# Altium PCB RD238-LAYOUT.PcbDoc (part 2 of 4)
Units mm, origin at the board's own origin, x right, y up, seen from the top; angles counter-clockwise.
Board outline 100 x 120 mm, 4 copper layers (Top Layer, GND2, POWER 3, Bottom Layer), stack 1.444 mm thick; 434 components, 174 nets, 1045 pads, 261 vias.
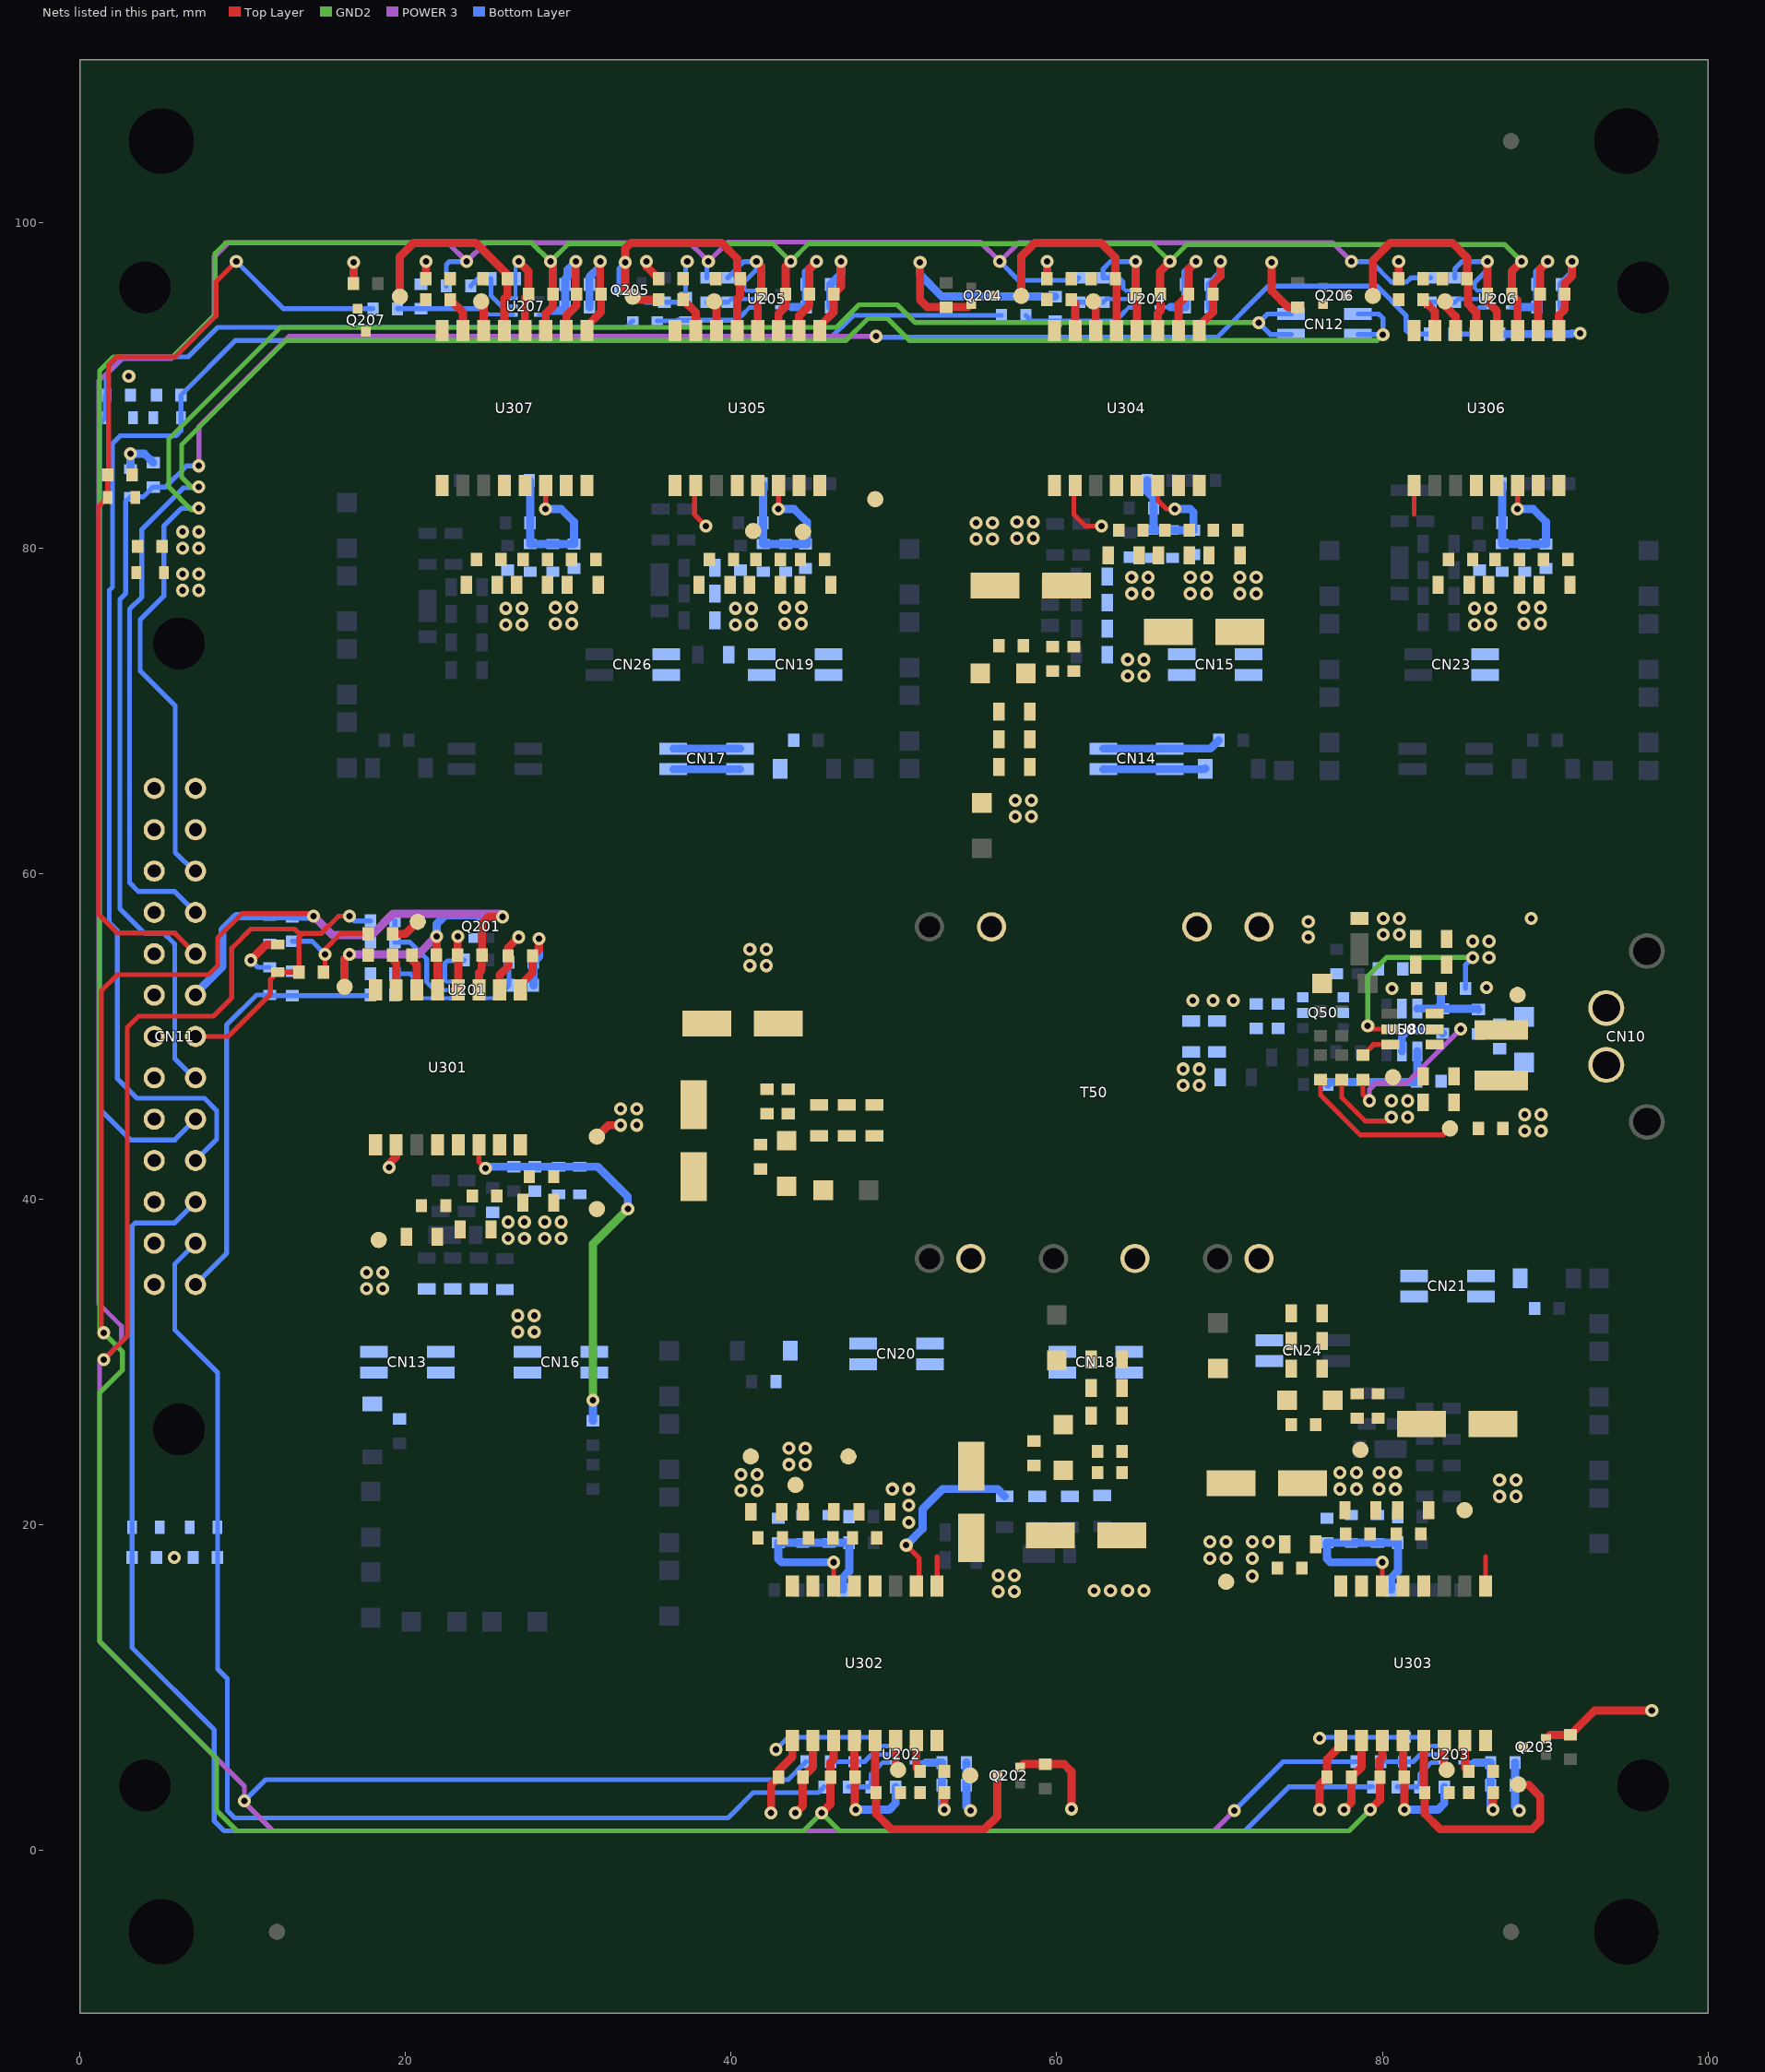
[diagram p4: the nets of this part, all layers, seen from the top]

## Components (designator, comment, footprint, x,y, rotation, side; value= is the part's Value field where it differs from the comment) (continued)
R351 "0" 1608 31.5,22.95 r90 bottom (schematic designator R35)
R352 "0" 1608 43.4,16 r0 bottom (schematic designator R35)
R353 "0" 1608 84,16 r180 bottom (schematic designator R35)
R354 "0" 1608 69,84.15 r180 bottom (schematic designator R35)
R355 "0" 1608 45.35,83.95 r180 bottom (schematic designator R35)
R356 "0" 1608 90.75,83.95 r180 bottom (schematic designator R35)
R357 "0" 1608 24.05,84.15 r0 bottom (schematic designator R35)
R361 "5.6" 2012 22.9,35.45 r90 bottom (schematic designator R36)
R362 "5.6" 2012 58.8,20.8 r270 bottom (schematic designator R36)
R363 "5.6" 2012 84.25,26.2 r270 bottom (schematic designator R36)
R364 "5.6" 2012 62.15,78.25 r180 bottom (schematic designator R36)
R365 "5.6" 2012 38.05,78.8 r180 bottom (schematic designator R36)
R366 "5.6" 2012 83.45,80.25 r180 bottom (schematic designator R36)
R367 "5.6" 2012 23.75,77.6 r180 bottom (schematic designator R36)
R371 "5.6" 2012 21.3,35.45 r90 bottom (schematic designator R37)
R372 "5.6" 2012 56.8,20.8 r270 bottom (schematic designator R37)
R373 "5.6" 2012 82.6,26.2 r270 bottom (schematic designator R37)
R374 "5.6" 2012 62.15,76.65 r180 bottom (schematic designator R37)
R375 "5.6" 2012 38.05,77.2 r180 bottom (schematic designator R37)
R376 "5.6" 2012 83.45,78.65 r180 bottom (schematic designator R37)
R377 "5.6" 2012 23.75,75.95 r180 bottom (schematic designator R37)
R381 "0" 1608 19.628,25.762 r270 bottom (schematic designator R38)
R382 "0" 1608 42,28.8 r180 bottom (schematic designator R38)
R383 "0" 1608 90.1,33.3 r0 bottom (schematic designator R38)
R384 "0" 1608 70.7,68.2 r0 bottom (schematic designator R38)
R385 "0" 1608 44.6,68.2 r0 bottom (schematic designator R38)
R386 "0" 1608 90,68.2 r0 bottom (schematic designator R38)
R387 "0" 1608 19.45,68.2 r180 bottom (schematic designator R38)
R391 "10" 2012 26.1,35.4 r90 bottom (schematic designator R39)
R392 "10" 2012 60.8,20.8 r270 bottom (schematic designator R39)
R393 "10" 2012 80.8,27.15 r270 bottom (schematic designator R39)
R394 "10" 2012 62.15,75.05 r180 bottom (schematic designator R39)
R395 "10" 2012 38.05,75.55 r180 bottom (schematic designator R39)
R396 "10" 2012 83.45,77.05 r180 bottom (schematic designator R39)
R397 "10" 2012 23.75,74.2 r180 bottom (schematic designator R39)
R401 "10" 2012 24.5,35.45 r90 bottom (schematic designator R40)
R402 "10" 2012 62.8,20.85 r270 bottom (schematic designator R40)
R403 "10" 2012 79.05,27.15 r270 bottom (schematic designator R40)
R404 "10" 2012 62.15,73.45 r180 bottom (schematic designator R40)
R405 "10" 2012 38.9,73.45 r180 bottom (schematic designator R40)
R406 "10" 2012 83.45,75.45 r180 bottom (schematic designator R40)
R407 "10" 2012 23.75,72.5 r180 bottom (schematic designator R40)
T50 "750315038" 750315038 62.3,46.55 r270 top
TP10 "5V" TESTPAD_C1 84.15,44.35 r270 top
TP11 "GND" TESTPAD_C1 80.65,47.5 r90 top
TP12 "ABU" TESTPAD_C1 62.25,95.15 r90 top
TP13 "CBU" TESTPAD_C1 57.816,95.489 r90 top
TP14 "ATU" TESTPAD_C1 20.75,57.05 r90 top
TP15 "CTU" TESTPAD_C1 16.25,53.05 r90 top
TP16 "VCC2U" TESTPAD_C1 31.75,39.4 r90 top
TP17 "VEU" TESTPAD_C1 31.75,43.85 r90 top
TP18 "VEEU" TESTPAD_C1 18.35,37.5 r90 top
TP19 "VCC2V" TESTPAD_C1 47.2,24.2 r90 top
TP20 "VEV" TESTPAD_C1 43.95,22.45 r90 top
TP21 "VEEV" TESTPAD_C1 41.2,24.2 r90 top
TP22 "ATV" TESTPAD_C1 50.25,4.95 r270 top
TP23 "ABV" TESTPAD_C1 38.95,95.15 r90 top
TP24 "CTV" TESTPAD_C1 54.684,4.611 r270 top
TP25 "CBV" TESTPAD_C1 33.95,95.45 r90 top
TP26 "VCC2W" TESTPAD_C1 70.4,16.5 r90 top
TP27 "VEW" TESTPAD_C1 78.65,24.6 r90 top
TP28 "VEEW" TESTPAD_C1 85.05,20.9 r90 top
TP29 "ATW" TESTPAD_C1 83.95,4.95 r270 top
TP30 "CTW" TESTPAD_C1 88.35,4.05 r270 top
TP31 "ABW" TESTPAD_C1 83.85,95.15 r90 top
TP32 "CBW" TESTPAD_C1 79.416,95.489 r90 top
TP33 "VCC2B" TESTPAD_C1 41.35,81.05 r90 top
TP34 "VEB" TESTPAD_C1 44.4,81 r90 top
TP35 "VEEB" TESTPAD_C1 48.85,83 r90 top
TP36 "ABR" TESTPAD_C1 24.65,95.15 r90 top
TP37 "CBR" TESTPAD_C1 19.65,95.45 r90 top
TP80 "SW2" TESTPAD_C1 88.3,52.55 r0 top
U50 "LT8306" TSOT23-6 81.2,50.4 r180 bottom
U80 "LMR51430XDDCR" SOT23-6 81.85,50.45 r180 top
U201 "TC7SZ08FE" SOT-553ESV 23.8,52.85 r0 bottom (schematic designator U20)
U202 "TC7SZ08FE" SOT-553ESV 50.462,5.9 r0 bottom (schematic designator U20)
U203 "TC7SZ08FE" SOT-553ESV 84.162,5.9 r0 bottom (schematic designator U20)
U204 "TC7SZ08FE" SOT-553ESV 65.5,95.3 r0 bottom (schematic designator U20)
U205 "TC7SZ08FE" SOT-553ESV 42.2,95.3 r0 bottom (schematic designator U20)
U206 "TC7SZ08FE" SOT-553ESV 87.1,95.3 r0 bottom (schematic designator U20)
U207 "TC7SZ08FE" SOT-553ESV 27.4,94.85 r0 bottom (schematic designator U20)
U301 "TLP5222" SO16L 22.6,48.1 r270 top (schematic designator U30)
U302 "TLP5222" SO16L 48.2,11.5 r90 top (schematic designator U30)
U303 "TLP5222" SO16L 81.9,11.5 r90 top (schematic designator U30)
U304 "TLP5222" SO16L 64.3,88.6 r270 top (schematic designator U30)
U305 "TLP5222" SO16L 41,88.6 r270 top (schematic designator U30)
U306 "TLP5222" SO16L 86.4,88.6 r270 top (schematic designator U30)
U307 "TLP5222" SO16L 26.7,88.6 r270 top (schematic designator U30)
? "Comment" FD 87.9,-5 r180 bottom
? "Comment" FD 12.1,-5 r180 bottom
? "Comment" FD 12.1,-5 r0 top
? "Comment" FD 87.9,-5 r0 top
? "Comment" FD 87.9,105 r180 bottom
? "Comment" FD 87.9,105 r0 top

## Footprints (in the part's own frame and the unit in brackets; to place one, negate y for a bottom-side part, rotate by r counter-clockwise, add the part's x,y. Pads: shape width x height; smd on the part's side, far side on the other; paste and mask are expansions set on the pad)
1608 [mm]
  rect 0.7x0.8 smd mask+0: 1(-0.75,0) 2(0.75,0)
  silkscreen extent -1.33,-0.63 1.33,0.63
2012 [mm]
  rect 0.7x1.1 smd mask+0: 1(-0.95,0) 2(0.95,0)
  silkscreen extent -1.53,-0.77 1.53,0.77
4020 [mm]
  rect 1.2x3.3 smd mask+0: 1(-1.55,0) 2(1.55,0)
  silkscreen extent -2.53,-2.3 2.53,2.3
750315038 [mm]
  round 1.8 hole 1.3 mask+0: 1(-10.19,10.12) 2(-10.19,6.31) 5(-10.19,-6.31) 6(-10.19,-10.12) 7(10.19,-10.12) 8(10.19,-7.58) 10(10.19,-2.5) 11(10.19,2.5) 13(10.19,7.58) 14(10.19,10.12)
  silkscreen extent -13.46,-11.96 12.21,11.96
62300421021 [mm]
  rect 0.74x1.7 smd mask+0: 1(-0.635,-2.05) 2(-0.635,2.05) 3(0.635,-2.05) 4(0.635,2.05)
  silkscreen extent -1.77,-3.94 1.77,3.28
ESC [mm]
  rect 0.6x0.8 smd mask+0: 1(-0.85,0) 2(0.85,0)
  silkscreen extent -1.78,-0.78 1.53,0.78
FD [mm]
  round 1 smd mask+0: 1(0,0)
  Keep-Out Layer circle w0.05: c0,0 r1.6
S-FLAT [mm]
  rect 1.2x1.2 smd mask+0: 1(-1.4,0) 2(1.4,0)
  silkscreen extent -2.38,-0.98 2.67,0.98
SMD [mm]
  rect 3x1.6 smd mask+0: 1(2.2,0) 2(-2.2,0)
  silkscreen extent -4.08,-2.95 4.08,2.95
SO16L [mm]
  rect 1.3x0.8 smd mask+0: 1(-4.75,4.445) 2(-4.75,3.175) 3(-4.75,1.905) 4(-4.75,0.635) 5(-4.75,-0.635) 6(-4.75,-1.905) 7(-4.75,-3.175) 8(-4.75,-4.445) 9(4.75,-4.445) 10(4.75,-3.175) 11(4.75,-1.905) 12(4.75,-0.635) 13(4.75,0.635) 14(4.75,1.905) 15(4.75,3.175) 16(4.75,4.445)
  silkscreen extent -5.78,-5.45 5.78,5.45
SOD-123 [mm]
  rect 0.91x1.22 smd mask+0: 1(-1.635,0) 2(1.635,0)
  silkscreen extent -2.79,-1.1 2.47,1.1
SOD-323HE [mm]
  rect 0.8x1.1 smd mask+0: 1(1.25,0)
  rect 2x1.1 smd mask+0: 2(-0.65,0)
  silkscreen extent -2.03,-1 2.03,1
SOT23-6 [mm]
  rect 1.1x0.6 smd mask+0: 1(-1.35,0.95) 2(-1.35,0) 3(-1.35,-0.95) 4(1.35,-0.95) 5(1.35,0) 6(1.35,0.95)
  silkscreen extent -2.79,-1.75 2.28,1.75
SOT-553ESV [mil]
  rect 25x10 smd mask+0: 1(-31.97,19.69) 2(-31.98,0) 3(-31.97,-19.68) 4(31.97,-19.68) 5(31.97,19.69)
  silkscreen extent -75,-43 59,43
SSM [mm]
  rect 0.6x0.6 smd mask+0: 1(-0.7,0.5) 2(-0.7,-0.5) 3(0.7,0)
  silkscreen extent -1.38,-1.18 1.38,1.18
TESTPAD_C1 [mm]
  round 1 smd paste-2539.97 mask+0: 1(0,0)
  silkscreen extent -0.77,-0.77 0.77,0.77
TSOP6F [mm]
  rect 0.7x0.62 smd mask+0: 1(-1.25,0.95) 2(-1.25,0) 3(-1.25,-0.95) 4(1.25,-0.95) 5(1.25,0) 6(1.25,0.95)
  silkscreen extent -2.41,-1.64 1.98,1.64
TSOT23-6 [mm]
  rect 0.62x1.22 smd mask+0: 1(-0.95,-1.31) 2(0,-1.31) 3(0.95,-1.31) 4(0.95,1.31) 5(0,1.31) 6(-0.95,1.31)
  silkscreen extent -1.75,-2.31 1.75,2.31
XG4A-2632 [mm]
  round 1.3 hole 0.8 mask+0: 1(0,0) 2(0,2.54) 3(2.54,0) 4(2.54,2.54) 5(5.08,0) 6(5.08,2.54) 7(7.62,0) 8(7.62,2.54) 9(10.16,0) 10(10.16,2.54) 11(12.7,0) 12(12.7,2.54) 13(15.24,0) 14(15.24,2.54) 15(17.78,0) 16(17.78,2.54) 17(20.32,0) 18(20.32,2.54) 19(22.86,0) 20(22.86,2.54) 21(25.4,0) 22(25.4,2.54) 23(27.94,0) 24(27.94,2.54) 25(30.48,0) 26(30.48,2.54)
  round 3.2 hole 3.2 unplated mask+0: M1(-8.91,1) M2(39.39,1)
  silkscreen extent -11.34,-4.13 41.82,5.97
XW4M-02D1-V1DS [mm]
  round 2.2 hole 1.7 mask+0: 1(1.75,0) 2(-1.75,0) M1(5.25,-2.5) M2(-5.25,-2.5)
  silkscreen extent -8.75,-4.25 8.75,3.43

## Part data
C10 C53 C321 C322 C323 C324 C325 C326 C327 C331 C332 C333 C334 C335 C336 C337 C341 C342 C343 C344 C345 C346 C347: library part 1u/50V/1608, "Ceramic, 50V, 亇10 %, X7R"
C50 C52 C56 C57 C58 C59 C60 C61 C62 C63 C351 C352 C353 C354 C355 C356 C357 C361 C362 C363 C364 C365 C366 C367 C371 C372 C373 C374 C375 C376 C377: library part 10u/50V/2012, "Ceramic, 50V, 亇10 %, X5R"
C51 C54 C80: library part 1000p/50V/1608, "Ceramic, 50V, 亇10 %, X7R"
C55 C241 C242 C243 C244 C245 C246 C247: library part 470p/50V/1608, "Ceramic, 50V, 亇10 %, X7R"
C64 C65 C66 C67 C68 C69 C70 C71 C81 C231 C232 C233 C234 C235 C236 C237 C311 C312 C313 C314 C315 C316 C317: library part 100n/50V/1608/GCM, "Ceramic, 50V, 亇10 %, X7R"
C72 C73 C74 C75 C76 C77 C78 C79: library part 47u/35V/ALUM/CHEMI-CON, "Aluminum, 35V, 亇20 %, -55亱C乣105亱C"
C82 C83: library part 4u7/50V/2012, "Ceramic, 50V, 亇10 %, X7R"
C84 C85: library part 22u/25V/2012, "Ceramic, 25V, 亇20 %, X5R"
C201 C202 C203 C204 C205 C206 C207 C211 C212 C213 C214 C215 C216 C217 C381 C382 C383 C384 C385 C386 C387: library part 100p/50V/1608, "Ceramic, 50V, 亇10 %, X7R"
C221 C222 C223 C224 C225 C226 C227: library part 1u/25V/1608, "Ceramic, 25V, 亇10 %, X7R"
C301 C302 C303 C304 C305 C306 C307: library part 1000p/25V/1608, "Ceramic, 25V, 亇10 %, X7R"
CN10: library part "XW4M-02D1-V1DS, 2PIN, 1楍", "CONNECTOR"
CN11: library part "XG4A-2632, 26PIN, 2楍", "CONNECTOR"
CN12 CN13 CN14 CN15 CN16 CN17 CN18 CN19 CN20 CN21 CN22 CN23 CN24 CN25 CN26: library part "62300421021, 4PIN, 2楍", "Receptacle Connector"
D10 D11 D12 D201 D202 D203 D204 D205 D206 D207: library part CEZ6V8, "Zener Diode"
D13: library part CRZ36, "Zener Diode"
D50 D56 D57 D58 D59 D301 D302 D303 D304 D305 D306 D307 D371 D372 D373 D374 D375 D376 D377: "Zener Diode"
D51 D311 D312 D313 D314 D315 D316 D317 D361 D362 D363 D364 D365 D366 D367: "SBD"
D52 D53 D54 D55: "Rectifier Diode"
D321 D322 D323 D324 D325 D326 D327 D331 D332 D333 D334 D335 D336 D337 D341 D342 D343 D344 D345 D346 D347 D351 D352 D353 D354 D355 D356 D357: "Fast Recovery Diode"
L80: library part 74405042047, "Inductor SMD"
Q50: "Nch-MOSFET"
Q201 Q202 Q203 Q204 Q205 Q206 Q207: library part SSM3K15AFS, "Nch-MOSFET"
R10 R11 R53 R55 R56 R57 R58 R351 R352 R353 R354 R355 R356 R357 R381 R382 R383 R384 R385 R386 R387: "Resistor"
R12 R13 R54 R201 R202 R203 R204 R205 R206 R207: library part 4K7, "Resistor"
R50: library part 330k, "Resistor"
R51: library part 33k, "Resistor"
R52: library part 100K/1%/0.1W/1608, "Resistor"
R59 R60 R61 R62: library part 2k2/2012/0.5W/1%, "Resistor"
R75 R76 R77 R78: library part 820/1608/0.125W/1%, "Resistor"
R80: library part 15k/1608/0.1W/1%, "Resistor"
R81: library part 82k/1608/0.1W/1%, "Resistor"
R82: library part 12k/1608/0.1W/1%, "Resistor"
R83: library part 1k2/1608/0.1W/1%, "Resistor"
R211 R212 R213 R214 R215 R216 R217 R221 R222 R223 R224 R225 R226 R227: library part 100R, "Resistor"
R231 R232 R233 R234 R235 R236 R237: library part 10K/1%, "Resistor"
R241 R242 R243 R244 R245 R246 R247: library part 330/1608/0.125W/1%, "Resistor"
R251 R252 R253 R254 R255 R256 R257: library part 2k2/1608/0.1W/1%, "Resistor"
R301 R302 R303 R304 R305 R306 R307: library part 18k/1608/0.1W/1%, "Resistor"
R311 R312 R313 R314 R315 R316 R317: library part 30K, "Resistor"
R321 R322 R323 R324 R325 R326 R327 R331 R332 R333 R334 R335 R336 R337 R391 R392 R393 R394 R395 R396 R397 R401 R402 R403 R404 R405 R406 R407: library part 10/2012/0.5W/1%, "Resistor"
R341 R342 R343 R344 R345 R346 R347: library part 470/1608/0.125W/1%, "Resistor"
R361 R362 R363 R364 R365 R366 R367 R371 R372 R373 R374 R375 R376 R377: library part 5R6/2012/0.5W/1%, "Resistor"
T50: "Transformer,   TH"
TP10 TP11 TP12 TP13 TP14 TP15 TP16 TP17 TP18 TP19 TP20 TP21 TP22 TP23 TP24 TP25 TP26 TP27 TP28 TP29 TP30 TP31 TP32 TP33 TP34 TP35 TP36 TP37 TP80: library part "TEST PAD 兂1", "PAD"
U50: "CV and CC Flyback Controller with Primary-Side Regulation"
U80: "Synchronous Buck Concerter SOT-23-6"
U201 U202 U203 U204 U205 U206 U207: "1 AND logic"
U301 U302 U303 U304 U305 U306 U307: "Gate-Driver"

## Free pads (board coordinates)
  round 3.2 hole 3.2 unplated mask+0: 0(96,96) NTH3(4,4) NTH3(4,96) NTH3(96,4)
  round 4 hole 4 unplated mask+0: NTH3(5,-5) NTH3(5,105) NTH3(95,-5) NTH3(95,105)

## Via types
v1: diameter 0.8, hole 0.4, Top Layer to Bottom Layer, 261 vias

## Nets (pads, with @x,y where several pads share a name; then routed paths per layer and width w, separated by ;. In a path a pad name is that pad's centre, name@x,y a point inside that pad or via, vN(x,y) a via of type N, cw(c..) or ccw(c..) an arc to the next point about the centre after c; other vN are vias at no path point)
GND: C10.1 C50.1 C51.1 C52.1 C53.1 C54.1 C80.1 C82.1 C83.1 C84.1 C85.1 C201.1 C202.1 C203.1 C204.1 C205.1 C206.1 C207.1 C211.1 C212.1 C213.1 C214.1 C215.1 C216.1 C217.1 C221.1 C222.1 C223.1 C224.1 C225.1 C226.1 C227.1 C231.1 C232.1 C233.1 C234.1 C235.1 C236.1 C237.1 C301.2 C302.2 C303.2 C304.2 C305.2 C306.2 C307.2 C311.2 C312.2 C313.2 C314.2 C315.2 C316.2 C317.2 CN10.2 CN11.2 CN11.4 CN11.6 CN11.8 CN11.10 CN11.12 CN11.14 CN11.16 CN11.18 CN11.20 CN11.22 CN11.24 CN11.26 D10.2 D11.2 D12.2 D13.1 D201.2 D202.2 D203.2 D204.2 D205.2 D206.2 D207.2 Q201.2 Q202.2 Q203.2 Q204.2 Q205.2 Q206.2 Q207.2 R51.1 R58.1 R83.1 R201.1 R202.1 R203.1 R204.1 R205.1 R206.1 R207.1 R231.1 R232.1 R233.1 R234.1 R235.1 R236.1 R237.1 TP11.1 U50.2 U80.1 U201.3 U202.3 U203.3 U204.3 U205.3 U206.3 U207.3 U301.1 U301.4 U302.1 U302.4 U303.1 U303.4 U304.1 U304.4 U305.1 U305.4 U306.1 U306.4 U307.1 U307.4 | length 182.1
  Top Layer w0.3: R83.1@77.5,47.35 77.5,46.25 78.95,44.8 80.3,44.8 v1(80.55,45.05)
  Top Layer w0.5: v1(10.485,54.685) 11.45,55.65 D12.2@12.15,55.65 ; R237.1@16.8,96.25 v1(16.8,97.55) ; C301.2@23.2,55 v1(23.2,56.15) ; U301.4@23.235,52.85 C301.2@23.235,55 ; v1(26.95,97.6) 27.55,97 C307.2@27.55,95.6 ; U301.1@27.045,52.85 27.045,53.145 27.8,53.9 C311.2@27.8,54.95 28.2,55.35 v1(28.2,56) ; U307.4@27.335,93.35 C307.2@27.335,95.385 ; U307.1@31.145,93.35 31.145,93.645 32,94.5 C317.2@32,95.6 31.95,95.65 v1(31.95,97.6) ; v1(41.55,97.6) 41.85,97.3 C305.2@41.85,95.6 41.635,95.385 U305.4@41.635,93.35 ; v1(42.45,2.3) 42.45,4.05 C312.2@42.9,4.5 42.9,4.9 43.755,5.755 U302.1@43.755,6.75 ; U305.1@45.445,93.35 45.445,93.645 46.3,94.5 C315.2@46.3,95.6 46.75,96.05 v1(46.75,97.6) ; U302.4@47.565,6.75 47.565,4.535 C302.2@47.6,4.5 47.6,2.55 v1(47.65,2.5) ; v1(51.6,97.55) 51.6,95.25 52.05,94.8 R234.1@53.2,94.8 Q204.2@54.55,94.8 ; Q202.2@57.95,5.3 60.45,5.3 60.9,4.85 v1(60.9,2.55) ; v1@64.866,97.584 v1(64.85,97.6) C304.2@64.85,95.6 64.935,95.515 U304.4@64.935,93.35 ; U304.1@68.745,93.35 68.745,93.645 69.6,94.5 C314.2@69.6,95.6 69.6,96.25 70.05,96.7 v1(70.05,97.6) ; v1(73.2,97.55) 73.2,95.8 74.2,94.8 R236.1@74.8,94.8 ; v1(76.15,2.5) 76.15,4.05 C313.2@76.6,4.5 76.6,5.6 77.455,6.455 U303.1@77.455,6.75 ; U303.4@81.265,6.75 81.265,4.585 C303.2@81.35,4.5 v1(81.35,2.5) ; v1(86.45,97.6) C306.2@86.45,95.6 86.45,95.15 87.035,94.565 87.035,93.8 U306.4@87.035,93.35 ; Q203.2@90.3,7.1 R233.1@91.55,7.1 93.05,8.6 v1(96.55,8.6) ; U306.1@90.845,93.35 90.845,94.295 91.2,94.65 C316.2@91.2,95.6 91.2,96.25 91.65,96.7 v1(91.65,97.6)
  Bottom Layer w0.25: 22.395,53.505 22.55,53.35 U201.3@22.988,53.35 ; U207.3@26.588,95.35 26.638,95.35 26.75,95.462 C217.1@26.75,96.55 26.75,97.4 v1(26.95,97.6) ; 40.783,95.967 40.95,95.8 U205.3@41.388,95.8 ; 49.045,6.567 49.212,6.4 U202.3@49.65,6.4 ; 64.083,95.967 64.25,95.8 U204.3@64.688,95.8 ; 82.745,6.567 82.912,6.4 U203.3@83.35,6.4 ; 85.683,96.333 85.683,95.967 85.85,95.8 U206.3@86.288,95.8
  Bottom Layer w0.3: v1(10.485,54.685) 10.919,54.25 D201.2@11.65,54.25 ; 22.395,53.505 22.395,54.47 22.575,54.65 23.55,54.65 R231.1@23.6,54.7 ; Q205.2@34.5,95.35 34.75,95.1 R235.1@35.9,95.1 36.9,95.1 C205.1@37.2,95.4 37.2,97.5 v1(37.3,97.6) ; C215.1@39.8,96.6 39.8,96.625 40.775,97.6 v1(41.55,97.6) 41.55,97.1 40.783,96.333 40.783,95.967 ; v1@42.85,6.3 43.5,6.95 C212.1@47.6,6.95 48.662,6.95 49.045,6.567 ; 64.083,95.967 64.083,96.333 63.816,96.6 C214.1@62.85,96.6 62.85,97.15 63.3,97.6 v1(64.85,97.6) ; v1(76.15,6.9) 76.2,6.95 82.362,6.95 82.745,6.567 ; C216.1@84.45,96.6 84.45,97.15 84.9,97.6 v1(86.45,97.6) 86.45,97.1 85.683,96.333
  Bottom Layer w0.5: D206.2@3.1,84.85 v1(3.1,85.8) 3.95,85.8 R206.1@4.5,85.25 ; C231.1@27.85,53.15 C221.1@27.85,54.55 28.2,54.9 v1(28.2,56) ; C237.1@31.3,94.8 C227.1@31.3,96.2 31.3,96.65 31.95,97.3 v1(31.95,97.6) ; C235.1@46.1,94.8 C225.1@46.1,96.2 46.75,96.85 v1(46.75,97.6) ; v1(47.65,2.5) 49.7,2.5 50.1,2.9 C202.1@50.1,3.9 ; v1(51.6,97.55) 51.6,96.8 52.95,95.45 C204.1@59.9,95.45 ; C232.1@54.45,5.4 54.45,2.7 v1(54.7,2.45) ; C234.1@69.4,94.8 C224.1@69.4,96.2 70.05,96.85 v1(70.05,97.6) ; U50.2@81.2,49.09 81.2,50 81.55,50.35 83.55,50.35 R51.1@83.7,50.2 ; v1(81.35,2.5) 83.4,2.5 83.8,2.9 C203.1@83.8,3.9 ; C206.1@87.2,93.15 91.6,93.15 91.65,93.2 ; C233.1@88.15,5.4 88.15,2.7 v1(88.4,2.45) ; C236.1@91,94.8 C226.1@91,96.2 91.65,96.85 v1(91.65,97.6)
  other v1: 42.75,6.2 5.8,18 81.55,45.05 80.55,46.05 81.55,46.05 67.75,47 68.75,47 67.75,48 68.75,48 80.05,56.25 81.05,56.25 80.05,57.25 81.05,57.25 89.15,57.25 6.3,77.4 7.3,77.4 6.3,78.4 7.3,78.4 3,90.55 92.15,93.2
NC_LED_BOTU: U304.15
NC_LED_BOTV: U305.15
NC_LED_BOTW: U306.15
NC_LED_BR: U307.15
NC_LED_TOPU: U301.15
NC_LED_TOPV: U302.15
NC_LED_TOPW: U303.15
NetC10_2: C10.2 C50.2 C52.2 C53.2 C80.2 C82.2 C83.2 CN10.1 D13.2 D50.1 R50.2 R53.2 T50.1 U50.5 U80.3 U80.5 | length 13.5
  Top Layer w0.3: v1(79.1,50.65) 79.3,50.45 U80.5@80.5,50.45
  GND2 w0.3: v1(79.1,50.65) 79.1,53.7 80.25,54.85 v1(85.55,54.85)
  Bottom Layer w0.3: R50.2@85.1,52.95 85.1,54.4 v1(85.55,54.85)
  other v1: 68.35,52.2 69.6,52.2 70.85,52.2 80.6,52.95 86.4,53 86.55,54.85 85.55,55.85 86.55,55.85
NetC51_2: C51.2 R50.1 R51.2 U50.6 | length 4.9
  Bottom Layer w0.5: U50.6@82.15,51.71 R51.2@83.6,51.71 ; R51.2@83.6,51.77 83.67,51.7 R51.2@83.7,51.7 85.85,51.7 C51.2@85.9,51.65 ; R51.2@83.6,51.85 R50.1@83.6,52.95
NetC54_2: C54.2 R56.2 U50.1 | length 7.4
  Bottom Layer w0.5: R56.2@76.65,47.05 76.8,47.2 82.05,47.2 C54.2@82.1,47.25 82.15,47.3 U50.1@82.15,49.09
NetC55_1: C55.1 D51.1 Q50.1 Q50.2 Q50.5 Q50.6 R54.1 T50.2
  other v1: 75.45,56.1 75.45,57.05
NetC55_2: C55.2 R53.1
NetC81_1: C81.1 L80.1 TP80.1 U80.2 | length 9.3
  Top Layer w0.3: C81.1@78.8,47.35 78.8,46.45 v1(79.2,46.05)
  POWER 3 w0.3: v1(79.2,46.05) 79.2,46.75 79.6,47.15 81.5,47.15 v1(84.8,50.45)
NetC81_2: C81.2 U80.6 | length 2
  Top Layer w0.3: C81.2@78.8,48.85 79.45,49.5 U80.6@80.5,49.5
NetC84_2: C84.2 C85.2 L80.2 R11.1 R81.1 TP10.1 | length 10.1
  Top Layer w0.3: R81.1@76.2,47.35 76.2,46.4 78.65,43.95 83.75,43.95 TP10.1@84.15,44.35
NetC201_2: C201.2 R211.1 U201.1 | length 6.1
  Bottom Layer w0.25: 20.95,52.35 U201.1@22.988,52.35
  Bottom Layer w0.3: R211.1@19.35,52.55 C201.2@19.35,53.85 20.3,53.85 20.5,53.65 20.5,52.8 20.95,52.35
NetC202_2: C202.2 R212.1 U202.1 | length 3.5
  Bottom Layer w0.25: 49.062,5.15 49.312,5.4 U202.1@49.65,5.4
  Bottom Layer w0.3: R212.1@47.2,3.9 C202.2@48.6,3.9 48.6,4.688 49.062,5.15
NetC203_2: C203.2 R213.1 U203.1 | length 3.5
  Bottom Layer w0.25: 82.762,5.15 83.012,5.4 U203.1@83.35,5.4
  Bottom Layer w0.3: R213.1@80.9,3.9 C203.2@82.3,3.9 82.3,4.688 82.762,5.15
NetC204_2: C204.2 R214.1 U204.1 | length 7.1
  Bottom Layer w0.25: 64.1,94.45 64.45,94.8 U204.1@64.688,94.8
  Bottom Layer w0.3: R214.1@58.1,94.3 58.45,93.95 C204.2@59.9,93.95 63.6,93.95 64.1,94.45
NetC205_2: C205.2 R215.1 U205.1 | length 6.3
  Bottom Layer w0.25: 40.85,94.5 41.15,94.8 U205.1@41.388,94.8
  Bottom Layer w0.3: R215.1@35.45,93.95 36.65,93.95 36.7,94 40.35,94 40.85,94.5
NetC206_2: C206.2 R216.1 U206.1 | length 3.4
  Bottom Layer w0.25: C206.2@85.7,93.15 85.7,94.55 85.95,94.8 U206.1@86.288,94.8
  Bottom Layer w0.3: R216.1@84.4,93.15 C206.2@85.7,93.15
NetC207_2: C207.2 R217.1 U207.1 | length 7.2
  Bottom Layer w0.25: 25.05,94.35 U207.1@26.588,94.35
  Bottom Layer w0.3: R217.1@19.5,94.7 C207.2@20.95,94.7 24.7,94.7 25.05,94.35
NetC211_2: C211.2 R221.1 U201.2 | length 7
  Bottom Layer w0.25: 21.8,52.85 U201.2@22.988,52.85
  Bottom Layer w0.3: R221.1@19.35,57.1 C211.2@19.35,55.8 20.25,55.8 21.3,54.75 21.3,53.35 21.8,52.85
NetC212_2: C212.2 R222.1 U202.2 | length 3.7
  Bottom Layer w0.25: 48.65,5.9 U202.2@49.65,5.9
  Bottom Layer w0.3: R222.1@46.1,5.45 C212.2@47.6,5.45 48.2,5.45 48.65,5.9
NetC213_2: C213.2 R223.1 U203.2 | length 3.6
  Bottom Layer w0.25: 82.35,5.9 U203.2@83.35,5.9
  Bottom Layer w0.3: R223.1@79.9,5.45 C213.2@81.35,5.45 81.9,5.45 82.35,5.9
NetC214_2: C214.2 R224.1 U204.2 | length 3.4
  Bottom Layer w0.25: C214.2@62.85,95.1 63.05,95.3 U204.2@64.688,95.3
  Bottom Layer w0.3: R224.1@61.35,95.1 C214.2@62.85,95.1
NetC215_2: C215.2 R225.1 U205.2 | length 3
  Bottom Layer w0.25: C215.2@39.8,95.1 40,95.3 U205.2@41.388,95.3
  Bottom Layer w0.3: R225.1@38.5,95.1 C215.2@39.8,95.1
NetC216_2: C216.2 R226.1 U206.2 | length 3.4
  Bottom Layer w0.25: C216.2@84.45,95.1 84.65,95.3 U206.2@86.288,95.3
  Bottom Layer w0.3: R226.1@82.95,95.1 C216.2@84.45,95.1
NetC217_2: C217.2 R227.1 U207.2 | length 4.1
  Bottom Layer w0.25: 25.9,94.85 U207.2@26.588,94.85
  Bottom Layer w0.3: R227.1@24,96.1 24.45,96.55 C217.2@25.25,96.55 25.25,95.5 25.9,94.85
NetC221_2: C221.2 C222.2 C223.2 C224.2 C225.2 C226.2 C227.2 C231.2 C232.2 C233.2 C234.2 C235.2 C236.2 C237.2 C311.1 C312.1 C313.1 C314.1 C315.1 C316.1 C317.1 R10.1 R11.2 R12.1 R13.1 R241.2 R242.2 R243.2 R244.2 R245.2 R246.2 R247.2 U201.5 U202.5 U203.5 U204.5 U205.5 U206.5 U207.5 U301.2 U302.2 U303.2 U304.2 U305.2 U306.2 U307.2 | length 78.3
  Top Layer w0.3: R13.1@14.95,53.95 15.05,54.05 v1(15.05,55.05) 15.05,55.35 16,56.3 R241.2@17.7,56.3
  Top Layer w0.5: R247.2@21.25,96.55 v1(21.25,97.6) ; U301.2@25.775,52.85 25.775,53.775 26.3,54.3 C311.1@26.3,54.95 26.3,55.45 v1(26.95,56.1) ; U307.2@29.875,93.35 29.875,94.275 30.5,94.9 C317.1@30.5,95.6 30.45,95.65 v1(30.45,97.6) ; v1(34.8,97.6) 34.8,97.3 R245.2@35.55,96.55 ; v1(43.95,2.3) 44.4,2.75 C312.1@44.4,4.5 45.025,5.125 U302.2@45.025,6.75 ; U305.2@44.175,93.35 44.175,94.275 44.8,94.9 C315.1@44.8,95.6 44.8,97.15 v1(45.25,97.6) ; v1(53.1,2.5) R242.2@53.1,3.55 ; R244.2@59.4,96.55 v1(59.4,97.6) ; U304.2@67.475,93.35 67.475,94.975 C314.1@68.1,95.6 68.1,97.15 v1(68.55,97.6) ; v1(77.65,2.5) 78.1,2.95 C313.1@78.1,4.5 78.725,5.125 U303.2@78.725,6.75 ; R246.2@81,96.55 v1(81,97.6) ; v1(86.8,2.5) R243.2@86.8,3.55 ; U306.2@89.575,93.35 89.575,95.475 C316.1@89.7,95.6 89.7,97.15 v1(90.15,97.6)
  Bottom Layer w0.25: U201.5@24.612,52.35 25.55,52.35 ; U207.5@28.212,94.35 28.687,94.35 28.908,94.571 ; U205.5@43.012,94.8 43.696,94.8 ; U202.5@51.274,5.4 51.958,5.4 ; U204.5@66.312,94.8 66.996,94.8 ; U203.5@84.974,5.4 85.658,5.4 ; U206.5@87.912,94.8 88.596,94.8
  Bottom Layer w0.3: R12.1@13.05,55.85 14.25,55.85 v1(15.05,55.05) ; 25.55,52.35 C231.2@26.35,53.15 26.35,55.5 v1(26.95,56.1)
  Bottom Layer w0.5: 28.908,94.571 29.571,94.571 C237.2@29.8,94.8 29.8,96.516 29.95,96.666 29.95,97.1 v1(30.45,97.6) ; 43.696,94.8 C235.2@44.6,94.8 44.6,96.95 v1(45.25,97.6) ; 51.958,5.4 C232.2@52.862,5.4 ; C232.2@52.95,5.4 52.95,2.65 v1(53.1,2.5) ; 66.996,94.8 C234.2@67.9,94.8 C224.2@67.9,96.2 67.9,96.95 v1(68.55,97.6) ; 85.658,5.4 C233.2@86.562,5.4 ; C233.2@86.65,5.4 86.65,2.65 v1(86.8,2.5) ; 88.596,94.8 C236.2@89.5,94.8 89.5,96.95 v1(90.15,97.6)
  other v1: 88.75,44.2 89.75,44.2 88.75,45.2 89.75,45.2 6.3,80 7.3,80 6.3,81 7.3,81
NetC241_1: C241.1 Q201.3 R251.1 TP15.1 U301.5 U301.8 | length 15
  Top Layer w0.5: TP15.1@16.25,53.05 16.25,54.75 v1(16.55,55.05) ; v1(21.9,56.15) R251.1@21.9,55 21.965,54.935 U301.5@21.965,52.85
  POWER 3 w0.5: v1(16.55,55.05) 20.8,55.05 v1(21.9,56.15)
  Bottom Layer w0.5: v1(21.9,56.15) 21.9,56.9 22.45,57.45 Q201.3@24.65,57.45
NetC241_2: C241.2 R241.1 R251.2 TP14.1 U301.6 U301.7 | length 5.8
  Top Layer w0.5: C241.2@19.2,54.75 19.425,54.525 U301.7@19.425,52.85 ; R241.1@19.2,56.3 20,56.3 TP14.1@20.75,57.05 ; R251.2@20.45,54.65 20.695,54.405 U301.6@20.695,52.85
NetC242_1: C242.1 Q202.3 R252.1 TP24.1 U302.5 U302.8 | length 15.2
  Top Layer w0.5: U302.5@48.835,6.75 48.835,3.615 R252.1@48.9,3.55 48.9,2.25 49.85,1.3 55.55,1.3 56.35,2.1 Q202.3@56.35,4.6
NetC242_2: C242.2 R242.1 R252.2 TP22.1 U302.6 U302.7 | length 3.9
  Top Layer w0.5: U302.6@50.105,6.75 50.105,5.195 TP22.1@50.35,4.95 ; U302.7@51.375,6.75 51.375,5.075 C242.2@51.6,4.85
NetC243_1: C243.1 Q203.3 R253.1 TP30.1 U303.5 U303.8 | length 15.4
  Top Layer w0.5: U303.5@82.535,6.75 82.535,3.615 R253.1@82.6,3.55 82.6,2.25 83.55,1.3 89.2,1.3 89.7,1.8 89.7,3.3 88.95,4.05 TP30.1@88.35,4.05
NetC243_2: C243.2 R243.1 R253.2 TP29.1 U303.6 U303.7 | length 3.9
  Top Layer w0.5: U303.6@83.805,6.75 83.805,5.095 TP29.1@83.95,4.95 ; U303.7@85.075,6.75 85.075,5.075 C243.2@85.3,4.85
NetC244_1: C244.1 Q204.3 R254.1 TP13.1 U304.5 U304.8 | length 13.5
  Top Layer w0.5: TP13.1@57.816,95.489 57.816,97.916 58.65,98.75 62.7,98.75 63.6,97.85 R254.1@63.6,96.55 63.665,96.485 U304.5@63.665,93.35
NetC244_2: C244.2 R244.1 R254.2 TP12.1 U304.6 U304.7 | length 3.9
  Top Layer w0.5: C244.2@60.9,95.25 61.125,95.025 U304.7@61.125,93.35 ; TP12.1@62.25,95.15 62.395,95.005 U304.6@62.395,93.35
NetC245_1: C245.1 Q205.3 R255.1 TP25.1 U305.5 U305.8 | length 18.7
  Top Layer w0.5: C245.1@35.55,95.25 34.15,95.25 TP25.1@33.95,95.45 33.5,95.9 v1(33.5,97.55) 33.5,98.408 33.842,98.75 39.4,98.75 40.373,97.777 40.373,96.727 R255.1@40.55,96.55 40.55,95.5 40.365,95.315 U305.5@40.365,93.35
  Bottom Layer w0.3: Q205.3@33.1,95.85 33.1,97.15 v1(33.5,97.55)
NetC245_2: C245.2 R245.1 R255.2 TP23.1 U305.6 U305.7 | length 4.1
  Top Layer w0.5: C245.2@37.05,95.25 37.825,94.475 U305.7@37.825,93.35 ; TP23.1@38.95,95.15 39.095,95.005 U305.6@39.095,93.35
NetC246_1: C246.1 Q206.3 R256.1 TP32.1 U306.5 U306.8 | length 13.5
  Top Layer w0.5: TP32.1@79.416,95.489 79.416,97.666 80.5,98.75 84.3,98.75 85.2,97.85 R256.1@85.2,96.55 85.265,96.485 85.265,94.985 85.592,94.658 85.765,94.485 85.765,94.25 U306.5@85.765,93.35
NetC246_2: C246.2 R246.1 R256.2 TP31.1 U306.6 U306.7 | length 4.3
  Top Layer w0.5: C246.2@82.5,95.25 83.225,94.525 U306.7@83.225,93.35 ; TP31.1@83.85,95.15 83.85,94.879 84.495,94.234 U306.6@84.495,93.35
NetC247_1: C247.1 Q207.3 R257.1 TP37.1 U307.5 U307.8 | length 13.7
  Top Layer w0.5: TP37.1@19.65,95.45 19.65,97.9 20.5,98.75 24.3,98.75 26.2,96.85 26.25,96.8 R257.1@26.25,96.55 26.25,95.5 26.065,95.315 U307.5@26.065,93.35
NetC247_2: C247.2 R247.1 R257.2 TP36.1 U307.6 U307.7 | length 4.1
  Top Layer w0.5: C247.2@22.75,95.25 23.525,94.475 U307.7@23.525,93.35 ; TP36.1@24.65,95.15 24.795,95.005 U307.6@24.795,93.35
NetC301_1: C301.1 C302.1 C303.1 C304.1 C305.1 C306.1 C307.1 CN11.15 D11.1 R12.2 U301.3 U302.3 U303.3 U304.3 U305.3 U306.3 U307.3 | length 354.4
  Top Layer w0.3: v1(1.45,31.8) 1.3,31.95 1.3,52.8 2.3,53.8 7.9,53.8 8.45,54.35 8.45,56.05 9.95,57.55 14.19,57.55 v1(14.35,57.39)
  Top Layer w0.5: U301.3@24.505,52.85 24.505,53.905 24.666,54.066 C301.1@24.666,55.039 ; C301.1@24.65,55.1 24.7,55.1 24.7,56.95 25.1,57.35 v1(25.95,57.35) ; U307.3@28.605,93.35 28.605,94.405 29.05,94.85 C307.1@29.05,95.6 29.05,97.45 v1(28.9,97.6) ; U305.3@42.905,93.35 42.905,94.405 43.35,94.85 43.35,97.3 ; v1(45.55,2.3) 46.1,2.85 C302.1@46.1,4.5 46.1,5.4 46.295,5.595 U302.3@46.295,6.75 ; U304.3@66.205,93.35 66.205,94.405 66.366,94.566 C304.1@66.366,95.539 ; C304.1@66.35,95.6 66.35,97 v1(66.95,97.6) ; v1(79.25,2.5) 79.85,3.1 C303.1@79.85,4.5 ; C303.1@79.834,4.561 79.834,5.534 79.995,5.695 U303.3@79.995,6.75 ; C306.1@87.95,95.6 87.95,97 v1(88.55,97.6) ; C306.1@87.966,95.539 88.305,95.2 U306.3@88.305,93.35
  POWER 3 w0.5: v1(14.35,57.39) 15.5,56.24 17.94,56.24 19.24,57.54 25.76,57.54 v1(25.95,57.35)
  GND2 w0.3: v1(79.25,2.5) 77.95,1.2 46.65,1.2 v1(45.55,2.3) 44.45,1.2 9.65,1.2 8.4,2.45 8.4,5.65 1.2,12.85 1.2,28.1 2.6,29.5 2.6,30.65 v1(1.45,31.8) 1.2,32.05 1.2,90.9 2.05,91.75 5.7,91.75 8.3,94.35 8.3,98.103 8.947,98.75 27.75,98.75 v1(28.9,97.6) 30,98.7 42.55,98.7 43.4,97.85 v1(43.65,97.6) 44.75,98.7 65.85,98.7 v1(66.95,97.6) 68,98.65 87.5,98.65 v1(88.55,97.6)
  Bottom Layer w0.5: CN11.15@7,52.54 8.75,54.29 8.75,56.55 9.6,57.4 13,57.4 R12.2@13.05,57.35 v1@14.31,57.35
NetC321_1: C57.1 C61.1 C67.1 C75.1 C321.1 C331.1 C351.1 C361.1 R60.1 R76.1 T50.8 TP18.1 U301.9 U301.12
  other v1: 17.6,34.5 18.6,34.5 17.6,35.5 18.6,35.5 28.55,37.6 29.55,37.6 28.55,38.6 29.55,38.6 41.15,54.35 42.15,54.35 41.15,55.35 42.15,55.35
NetC321_2: C66.1 C67.2 C74.1 C75.2 C321.2 C341.2 C351.2 C371.2 C381.2 CN16.2 CN16.4 D57.1 D301.2 D311.1 R76.2 R301.2 TP17.1 U301.16 | length 1.7
  Top Layer w0.5: TP17.1@31.75,43.85 32.45,44.55 v1(33.2,44.55)
  other v1: 26.9,31.85 27.9,31.85 26.9,32.85 27.9,32.85 26.3,37.6 27.3,37.6 26.3,38.6 27.3,38.6 34.2,44.55 33.2,45.55 34.2,45.55
NetC322_1: C58.1 C62.1 C69.1 C77.1 C322.1 C332.1 C352.1 C362.1 R61.1 R77.1 T50.11 TP21.1 U302.9 U302.12 | length 3.6
  Top Layer w0.3: U302.9@52.645,16.25 52.645,18.045 U302.9@52.645,16.25
  other v1: 62.3,15.95 63.3,15.95 64.35,15.95 65.35,15.95 50.9,20.15 50.9,21.2 40.6,22.1 41.6,22.1 49.9,22.2 50.9,22.2 40.6,23.1 41.6,23.1
NetC322_2: C68.1 C69.2 C76.1 C77.2 C322.2 C342.2 C352.2 C372.2 C382.2 CN18.2 CN18.4 D58.1 D302.2 D312.1 R77.2 R302.2 TP20.1 U302.16
  other v1: 56.4,15.901 57.4,15.901 56.4,16.901 57.4,16.901 43.55,23.7 44.55,23.7 43.55,24.7 44.55,24.7
NetC323_1: C59.1 C63.1 C71.1 C79.1 C323.1 C333.1 C353.1 C363.1 R62.1 R78.1 T50.14 TP28.1 U303.9 U303.12 | length 3.6
  Top Layer w0.3: U303.9@86.345,16.25 86.345,18.045 U303.9@86.345,16.25
  other v1: 72,16.85 72,17.95 72,18.95 73,18.95 87.2,21.75 88.2,21.75 87.2,22.75 88.2,22.75
NetC323_2: C70.1 C71.2 C78.1 C79.2 C323.2 C343.2 C353.2 C373.2 C383.2 CN24.2 CN24.4 D59.1 D303.2 D313.1 R78.2 R303.2 TP27.1 U303.16
  other v1: 77.4,22.2 78.4,22.2 77.4,23.2 78.4,23.2
NetC324_1: C56.1 C60.1 C65.1 C73.1 C324.1 C325.1 C326.1 C327.1 C334.1 C335.1 C336.1 C337.1 C354.1 C355.1 C356.1 C357.1 C364.1 C365.1 C366.1 C367.1 R59.1 R75.1 T50.5 TP35.1 U304.9 U304.12 U305.9 U305.12 U306.9 U306.12 U307.9 U307.12 | length 1.8
  Top Layer w0.3: 81.955,82.055 U306.9@81.955,83.85
  other v1: 57.45,63.5 58.45,63.5 57.45,64.5 58.45,64.5 64.35,72.15 65.35,72.15 64.35,73.15 65.35,73.15 71.25,77.2 72.25,77.2 71.25,78.2 72.25,78.2 57.55,80.6 58.55,80.6 57.55,81.6 58.55,81.6
NetC324_2: C64.1 C65.2 C72.1 C73.2 C324.2 C325.2 C326.2 C327.2 C344.2 C345.2 C346.2 C347.2 C354.2 C355.2 C356.2 C357.2 C374.2 C375.2 C376.2 C377.2 C384.2 C385.2 C386.2 C387.2 CN15.2 CN15.4 CN19.2 CN19.4 CN23.2 CN23.4 CN26.2 CN26.4 D56.1 D304.2 D305.2 D306.2 D307.2 D314.1 D315.1 D316.1 D317.1 R75.2 R304.2 R305.2 R306.2 R307.2 TP34.1 U304.16 U305.16 U306.16 U307.16
  other v1: 29.2,75.35 30.2,75.35 43.3,75.35 44.3,75.35 88.7,75.35 89.7,75.35 29.2,76.35 30.2,76.35 43.3,76.35 44.3,76.35 88.7,76.35 89.7,76.35 68.2,77.2 69.2,77.2 68.2,78.2 69.2,78.2
NetC331_2: C57.2 C61.2 C66.2 C74.2 C331.2 C341.1 C361.2 C371.1 D53.2 D57.2 R60.2 TP16.1 U301.13
NetC332_2: C58.2 C62.2 C68.2 C76.2 C332.2 C342.1 C362.2 C372.1 D54.2 D58.2 R61.2 TP19.1 U302.13
NetC333_2: C59.2 C63.2 C70.2 C78.2 C333.2 C343.1 C363.2 C373.1 D55.2 D59.2 R62.2 TP26.1 U303.13
  other v1: 69.4,17.95 70.4,17.95 69.4,18.95 70.4,18.95 79.8,22.2 80.8,22.2 79.8,23.2 80.8,23.2
NetC334_2: C56.2 C60.2 C64.2 C72.2 C334.2 C335.2 C336.2 C337.2 C344.1 C345.1 C346.1 C347.1 C364.2 C365.2 C366.2 C367.2 C374.1 C375.1 C376.1 C377.1 D52.2 D56.2 R59.2 TP33.1 U304.13 U305.13 U306.13 U307.13
  other v1: 26.15,75.3 27.15,75.3 40.25,75.3 41.25,75.3 85.65,75.3 86.65,75.3 26.15,76.3 27.15,76.3 40.25,76.3 41.25,76.3 85.65,76.3 86.65,76.3 64.6,77.2 65.6,77.2 64.6,78.2 65.6,78.2 55.05,80.55 56.05,80.55 55.05,81.55 56.05,81.55
NetC381_1: C381.1 D301.1 D311.2 R311.2 R341.2 U301.14 | length 25.8
  Top Layer w0.3: U301.14@24.505,43.35 24.505,42.295 v1(24.9,41.9)
  GND2 w0.5: v1(31.5,27.65) 31.5,37.25 v1(33.65,39.4)
  Bottom Layer w0.5: v1(24.9,41.9) 25,42 R311.2@26.65,42 C381.1@27.95,42 D311.2@29.4,42 D301.1@30.7,42 31.8,42 33.65,40.15 v1(33.65,39.4) ; R341.2@31.5,26.4 v1(31.5,27.65)
NetC382_1: C382.1 D302.1 D312.2 R312.2 R342.2 U302.14 | length 13.4
  Top Layer w0.3: U302.14@46.295,16.25 46.295,17.695 v1(46.3,17.7)
  Bottom Layer w0.5: D312.2@46,18.9 D302.1@44.4,18.9 C382.1@42.9,18.9 42.9,17.9 43.1,17.7 v1(46.3,17.7) ; D312.2@46,18.9 R312.2@47.25,18.9 47.25,17.15 46.85,16.75 R342.2@46.85,16
NetC383_1: C383.1 D303.1 D313.2 R313.2 R343.2 U303.14 | length 13.4
  Top Layer w0.3: U303.14@79.995,16.25 79.995,17.695 v1(80,17.7)
  Bottom Layer w0.5: v1(80,17.7) 76.8,17.7 76.6,17.9 C383.1@76.6,18.9 D303.1@78.1,18.9 D313.2@79.7,18.9 R313.2@80.95,18.9 80.95,17.15 80.55,16.75 R343.2@80.55,16
NetC384_1: C384.1 D304.1 D314.2 R314.2 R344.2 U304.14 | length 10.4
  Top Layer w0.3: U304.14@66.205,83.85 66.205,82.945 66.75,82.4 v1(67.25,82.4)
  Bottom Layer w0.5: R344.2@65.55,84.15 65.55,83.469 65.95,83.069 R314.2@65.95,82.45 65.95,81.25 D314.2@65.8,81.1 D304.1@67.1,81.1 C384.1@68.4,81.1 68.4,82.2 68.2,82.4 v1(67.25,82.4)
NetC385_1: C385.1 D305.1 D315.2 R315.2 R345.2 U305.14 | length 11.3
  Top Layer w0.3: v1(42.9,82.4) 42.905,82.405 U305.14@42.905,83.85
  Bottom Layer w0.5: R345.2@41.9,83.95 41.95,83.9 R315.2@41.95,81.55 41.95,80.271 D315.2@41.971,80.25 D305.1@43.35,80.25 44.65,80.25 44.65,81.607 43.857,82.4 v1(42.9,82.4)
NetC386_1: C386.1 D306.1 D316.2 R316.2 R346.2 U306.14 | length 11.3
  Top Layer w0.3: v1(88.3,82.4) 88.305,82.405 U306.14@88.305,83.85
  Bottom Layer w0.5: R346.2@87.3,83.95 87.35,83.9 R316.2@87.35,81.55 D316.2@87.35,80.25 D306.1@88.75,80.25 C386.1@90.05,80.25 90.05,81.607 89.257,82.4 v1(88.3,82.4)
NetC387_1: C387.1 D307.1 D317.2 R317.2 R347.2 U307.14 | length 11.5
  Top Layer w0.3: v1(28.6,82.4) 28.605,82.405 U307.14@28.605,83.85
  Bottom Layer w0.5: R347.2@27.6,84.15 27.65,84.1 R317.2@27.65,81.55 D317.2@27.65,80.25 D307.1@29.05,80.25 C387.1@30.35,80.25 30.35,81.607 29.557,82.4 v1(28.6,82.4)
NetCN11_1: CN11.1 D201.1 R201.2 R211.2 | length 26.5
  Bottom Layer w0.3: CN11.1@7.1,34.76 9,36.66 9,42.1 9,46.65 9,50.7 10.85,52.55 D201.1@11.65,52.55 11.7,52.5 R211.2@17.8,52.5 ; R211.2@17.8,52.5 R211.2@17.85,52.55 R211.2@17.8,52.5
NetCN11_3: CN11.3 D202.1 R202.2 R212.2 | length 74.3
  Bottom Layer w0.3: CN11.3@7.1,37.3 5.825,36.025 5.825,31.975 8.45,29.35 D202.1@8.45,19.85 R202.2@8.45,18 8.45,11.15 9.05,10.55 9.05,2.45 9.5,2 39.8,2 41.35,3.55 45.35,3.55 R212.2@45.7,3.9
NetCN11_5: CN11.5 D203.1 R203.2 R213.2 | length 115.7
  Bottom Layer w0.3: CN11.5@7.1,39.84 5.81,38.55 3.4,38.55 3.2,38.35 D203.1@3.2,19.85 R203.2@3.2,18 3.2,12.45 8.25,7.4 8.25,1.8 8.85,1.2 71.55,1.2 74.25,3.9 R213.2@79.4,3.9
NetCN11_7: CN11.7 D204.1 R204.2 R214.2 | length 109
  Bottom Layer w0.3: CN11.7@7.1,42.38 8.4,43.68 8.4,45.45 7.65,46.2 3.5,46.2 2.3,47.4 2.3,56.5 1.8,57 1.8,77.4 2,77.6 2,86.43 2.47,86.9 5.9,86.9 6.2,87.2 R204.2@6.2,89.4 9.56,92.76 45.96,92.76 47.5,94.3 R214.2@56.6,94.3
NetCN11_9: CN11.9 D205.1 R205.2 R215.2 | length 86.2
  Bottom Layer w0.3: CN11.9@7.1,44.92 5.83,43.65 3.1,43.65 1.2,45.55 1.2,87.65 D205.1@1.55,88 1.55,89.35 R205.2@1.6,89.4 1.6,90.65 2.7,91.75 6.65,91.75 8.46,93.56 33.56,93.56 R215.2@33.95,93.95
NetCN11_11: CN11.11 D206.1 R206.2 R216.2 | length 126.9
  POWER 3 w0.3: v1(7.3,85.05) 7.3,87.45 12.85,93 v1@48.9,93
  Bottom Layer w0.3: CN11.11@7,47.46 5.825,48.635 5.825,55.675 5.65,55.85 5.15,56.35 3.95,56.35 2.45,57.85 2.45,76.85 2.8,77.2 2.8,82.85 D206.1@3.1,83.15 3.9,83.15 R206.2@4.5,83.75 5.25,83.75 6.55,85.05 v1(7.3,85.05) ; v1(48.9,93.01) 48.96,92.95 69.85,92.95 73,96.1 79.65,96.1 81.45,94.3 81.45,93.4 81.7,93.15 R216.2@82.9,93.15
NetCN11_13: CN11.13 D12.1 R13.2 R221.2 R222.2 R223.2 R224.2 R225.2 R226.2 R227.2 | length 350.8
  Top Layer w0.3: v1(1.45,30.15) 2.9,31.6 2.9,50.55 3.6,51.25 8.2,51.25 9.325,52.375 9.325,55.425 10.5,56.6 13.185,56.6 13.45,56.335 13.7,56.335 ; CN11.13@7.1,50 9.1,50 11.704,52.604 11.704,53.504 D12.1@12.15,53.95 R13.2@13.45,53.95 13.45,56.085 13.7,56.335 ; v1(16.55,57.39) 15.89,57.39 14.835,56.335 13.7,56.335
  POWER 3 w0.3: v1(70.9,2.45) 69.65,1.2 11.85,1.2 10.1,2.95 v1(10.1,3.05) 10.1,3.95 1.2,12.85 1.2,29.9 v1(1.45,30.15) 2.55,31.25 2.55,32.2 1.16,33.59 1.16,90.26 2.55,91.65 5.6,91.65 8.25,94.3 8.25,97.9 9.1,98.75 22.6,98.75 v1(23.75,97.6) 24.9,98.75 37.45,98.75 38.325,97.875 v1(38.6,97.6) 39.8,98.8 55.3,98.8 v1(56.5,97.6) 57.65,98.75 76.95,98.75 v1(78.1,97.6)
  Bottom Layer w0.3: v1(10.1,3.05) 11.4,4.35 43.5,4.35 R222.2@44.6,5.45 ; v1(16.55,57.39) 16.84,57.1 R221.2@17.85,57.1 ; R227.2@22.5,96.1 22.5,97.4 22.7,97.6 v1(23.75,97.6) ; R225.2@38.5,96.6 38.5,97.5 v1(38.6,97.6) ; v1(56.5,97.6) 57.65,96.45 61.2,96.45 R224.2@61.35,96.6 ; v1(70.9,2.45) 73.9,5.45 R223.2@78.4,5.45 ; v1(78.1,97.6) 79.3,97.6 80.55,96.35 81.5,96.35 81.75,96.6 R226.2@82.95,96.6
NetCN11_17: CN11.17 D207.1 R207.2 R217.2 | length 62.3
  Top Layer w0.3: CN11.17@7.1,55.08 5.83,56.35 2.3,56.35 1.151,57.499 1.151,82.551 D207.1@1.7,83.1 R207.2@1.7,84.5 1.75,84.55 1.75,91.25 2.25,91.75 5.85,91.75 8.35,94.25 8.35,96.35 v1(9.6,97.6)
  Bottom Layer w0.3: v1(9.6,97.6) 12.5,94.7 R217.2@18,94.7
NetCN11_19: CN11.19 CN12.1 CN12.3 | length 116.6
  GND2 w0.3: v1@7.3,83.7 6.9,83.7 6.25,84.35 6.25,86.35 12.66,92.76 47.06,92.76 48.4,94.1 49.6,94.1 50.94,92.76 79.68,92.76 v1(80.035,93.115)
  Bottom Layer w0.3: CN11.19@7.1,57.62 5.82,58.9 3.6,58.9 3.05,59.45 3.05,76.25 3.8,77 3.8,77.9 3.8,81.15 6.35,83.7 v1@7.3,83.7 ; CN12.3@78.5,93.115 v1(80.035,93.115) 80.035,94.115 79.765,94.385 CN12.1@78.5,94.385
  other v1: 7.3,83.75
NetCN11_21: CN11.21 CN12.2 CN12.4 | length 106.4
  GND2 w0.3: v1@7.25,82.35 6.85,82.35 5.45,83.75 5.45,86.69 12.32,93.56 46.46,93.56 47.85,94.95 50.2,94.95 51.3,93.85 v1(72.4,93.85)
  Bottom Layer w0.3: CN11.21@7,60.16 5.85,61.31 5.85,70.3 5.65,70.5 3.7,72.45 3.7,75.6 5.15,77.05 5.15,77.9 5.15,81.35 6.25,82.45 v1(7.3,82.45) ; CN12.4@74.4,93.115 73.135,93.115 v1(72.4,93.85) 72.935,94.385 CN12.2@74.4,94.385
NetCN11_23: CN11.23 CN11.25 D10.1 R10.2
NetCN13_1: CN13.1 CN13.2 CN13.3 CN13.4 D371.2 R381.1
NetCN14_1: CN14.1 CN14.2 CN14.3 CN14.4 D374.2 R384.1 | length 13.6
  Bottom Layer w0.5: CN14.1@62.85,66.415 CN14.2@66.95,66.415 69.08,66.415 D374.2@69.115,66.45 ; CN14.3@62.85,67.685 CN14.4@66.95,67.685 69.435,67.685 R384.1@69.95,68.2
NetCN15_1: CN15.1 CN15.3 R364.1 R374.1 R394.1 R404.1 U304.10 | length 3.7
  Top Layer w0.3: U304.10@61.125,83.85 61.05,83.775 61.05,82.05 61.75,81.35 v1@62.6,81.35
  other v1: 62.746,81.35
NetCN16_1: CN16.1 CN16.3 R361.1 R371.1 R391.1 R401.1 U301.10 | length 1.6
  Top Layer w0.5: v1(19,41.95) 19,42.2 19.425,42.625 U301.10@19.425,43.35
NetCN17_1: CN17.1 CN17.2 CN17.3 CN17.4 D375.2 R385.1 | length 8.2
  Bottom Layer w0.5: CN17.1@36.45,66.415 CN17.2@40.55,66.415 ; CN17.3@36.45,67.685 CN17.4@40.55,67.685
NetCN18_1: CN18.1 CN18.3 R362.1 R372.1 R392.1 R402.1 U302.10 | length 11.3
  Top Layer w0.3: v1(50.75,18.75) 51.55,17.95 51.55,16.425 U302.10@51.375,16.25
  Bottom Layer w0.5: v1(50.75,18.75) 51.75,19.75 51.75,20.95 53,22.2 56.35,22.2 R372.1@56.8,21.75
NetCN19_1: CN19.1 CN19.3 R365.1 R375.1 R395.1 R405.1 U305.10 | length 2.8
  Top Layer w0.3: U305.10@37.825,83.85 37.75,83.775 37.75,82.05 v1(38.45,81.35)
NetCN20_1: CN20.1 CN20.2 CN20.3 CN20.4 D372.2 R382.1
NetCN21_1: CN21.1 CN21.2 CN21.3 CN21.4 D373.2 R383.1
